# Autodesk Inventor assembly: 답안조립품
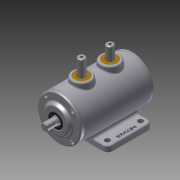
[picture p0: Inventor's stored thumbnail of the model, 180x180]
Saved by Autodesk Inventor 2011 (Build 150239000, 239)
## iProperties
Created: 2014-12
Part Number: 답안조립품
Document SubType Name: Assembly
Designer: user
Author: user
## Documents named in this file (9)
- D:\441225V1004\답안조립품.iam
- D:\441225V1004\1-본체.ipt
- D:\441225V1004\앞커버.ipt
- D:\441225V1004\베어링 6203.ipt
- D:\441225V1004\오일실.ipt
- D:\441225V1004\4-축.ipt
- D:\441225V1004\뒷커버.ipt
- D:\441225V1004\슬라이더.ipt
- D:\441225V1004\부시.ipt
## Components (5 placed, 4 different names)
1. 1-본체:1
2. 7-베어링 6203:1
3. 8-오일실:1 — 플러쉬:1
4. 4-축:1 — 플러쉬:1
5. 7-베어링 6203:2
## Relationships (1: Flush 1)
- 플러쉬:1 [Flush]: 8-오일실:1 ↔ 4-축:1
